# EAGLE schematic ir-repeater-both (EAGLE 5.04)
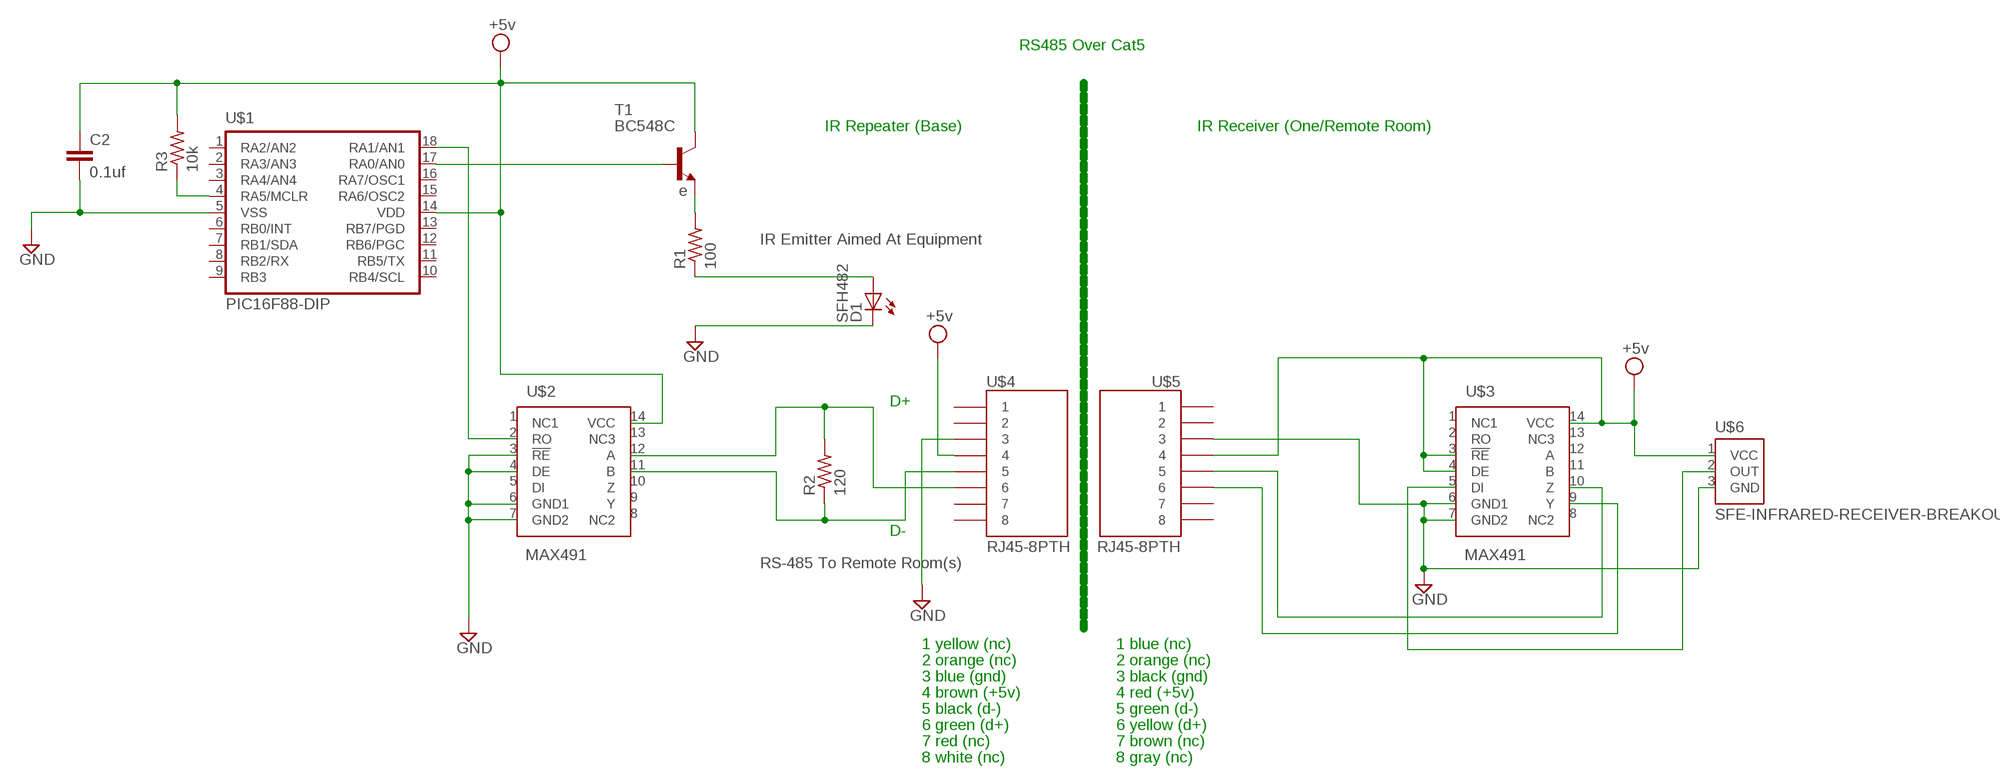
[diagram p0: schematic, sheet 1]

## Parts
C2  0.1uf  CAPPTH  [CAP-PTH-SMALL]
D1  SFH482  [SFH482]
R1  100  R-US_0411/15  [0411/15]
R2  120  R-US_0411/15  [0411/15]
R3  10k  R-US_0411/15  [0411/15]
T1  BC548C  BC548C-NPN-TO92-EBC  [TO92-EBC]
U$1  PIC16F88-DIP  [DIL18]
U$2  MAX491  [14DIP]
U$3  MAX491  [14DIP]
U$4  RJ45-8PTH  [RJ45-8]
U$5  RJ45-8PTH  [RJ45-8]
U$6  SFE-INFRARED-RECEIVER-BREAKOUT  [3SIL]

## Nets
GND: C2.2 D1.K(C) U$1.5(VSS) U$2.3(!RE) U$2.4(DE) U$2.6(GND1) U$2.7(GND2) U$3.6(GND1) U$3.7(GND2) U$4.3 U$5.3 U$6.3(GND)
N$1: T1.B U$1.17(RA0/AN0)
N$2: D1.A R1.1
N$3: R1.2 T1.E
N$4: U$1.18(RA1/AN1) U$2.2(RO)
N$5: R3.1 U$1.4(RA5/MCLR)
N$6: U$3.5(DI) U$6.2(OUT)
N$7: U$3.10(Z) U$5.5
N$8: R2.2 U$2.12(A) U$4.6
N$9: R2.1 U$2.11(B) U$4.5
N$11: U$3.9(Y) U$5.6
VCC: C2.1 R3.2 T1.C U$1.14(VDD) U$2.14(VCC) U$3.3(!RE) U$3.4(DE) U$3.14(VCC) U$4.4 U$5.4 U$6.1(VCC) ; supply symbol labelled +5v
Unconnected: U$1.1(RA2/AN2) U$1.2(RA3/AN3) U$1.3(RA4/AN4) U$1.6(RB0/INT) U$1.7(RB1/SDA) U$1.8(RB2/RX) U$1.9(RB3) U$1.10(RB4/SCL) U$1.11(RB5/TX) U$1.12(RB6/PGC) U$1.13(RB7/PGD) U$1.15(RA6/OSC2) U$1.16(RA7/OSC1) U$2.1(NC1) U$2.5(DI) U$2.8(NC2) U$2.9(Y) U$2.10(Z) U$2.13(NC3) U$3.1(NC1) U$3.2(RO) U$3.8(NC2) U$3.11(B) U$3.12(A) U$3.13(NC3) U$4.1 U$4.2 U$4.7 U$4.8 U$5.1 U$5.2 U$5.7 U$5.8

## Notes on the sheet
- RS485 Over Cat5
- IR Repeater (Base) | IR Receiver (One/Remote Room)
- e
- IR Emitter Aimed At Equipment
- D+
- D-
- RS-485 To Remote Room(s)
- 1 yellow (nc) | 1 blue (nc)
- 2 orange (nc) | 2 orange (nc)
- 3 blue (gnd) | 3 black (gnd)
- 4 brown (+5v) | 4 red (+5v)
- 5 black (d-) | 5 green (d-)
- 6 green (d+) | 6 yellow (d+)
- 7 red (nc) | 7 brown (nc)
- 8 white (nc) | 8 gray (nc)

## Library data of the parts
C2 = SparkFun:CAP: Capacitor
D1 = led:SFH482: IR LED
R1-R3 = resistor:R-US_: RESISTOR, American symbol
T1 = transistor:*-NPN-: NPN Transistror BF959 corrected 2008.03.06
U$1 = SparkFun:PIC16F88-DIP
U$2 U$3 = trl:MAX491
U$4 U$5 = SparkFun:RJ45-8: RJ45 Jack Simple RJ45, 8-pin connection - connector for common Cat5, Cat5e, and Cat6 Ethernet cables. Footprint not yet proven in production. Connector sku is PRT-00643; Breakout PCB sku is BOB-00716.
U$6 = trl:SFE-INFRARED-RECEIVER-BREAKOUT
